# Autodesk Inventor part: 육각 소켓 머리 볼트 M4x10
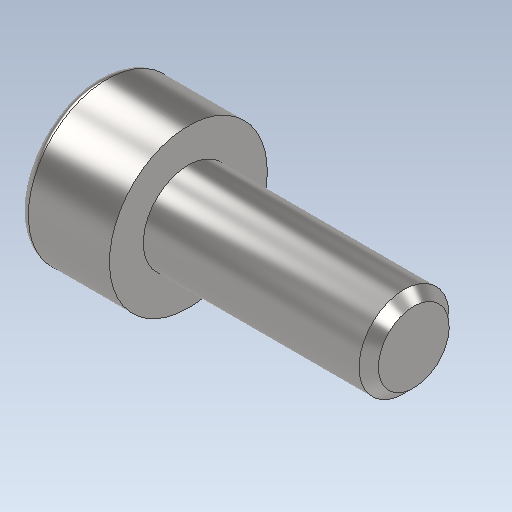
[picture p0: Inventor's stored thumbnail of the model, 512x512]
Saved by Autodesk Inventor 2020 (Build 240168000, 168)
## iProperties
Created: 2024-05
Part Number: 육각 소켓 머리 볼트 M4x10
Material: 강철, 연강
Description: 6각머리 태핑 나사
Document SubType Name: Modeling
Designer: oem
Density: 7.85 g/cm^3
Appearance: 기본값
Author: jhkim
Sending System: Autodesk Inventor 2025
Preprocessor: ST-DEVELOPER v20
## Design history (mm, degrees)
feature "Solid1"
node "솔리드1"
